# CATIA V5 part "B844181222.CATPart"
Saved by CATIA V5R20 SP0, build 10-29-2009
Part number: B844181222
Revision: 2
Definition: design
Nomenclature: B844181222
Source: made
Description: NOT SPECIFIED
Bounding box of the stored display mesh (mm): x -16.5 to 16.5, y -16.332 to 16.332, z -12 to 22
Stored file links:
  C:\Users\Utente\Desktop\3D files B844\B844181222.CATPart
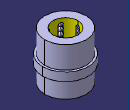
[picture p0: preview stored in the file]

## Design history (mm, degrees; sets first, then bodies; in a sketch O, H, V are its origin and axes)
Body1 "MANIFOLD_SOLID_BREP #38" (main body)
  Solid1: solid without history
Body2 "MANIFOLD_SOLID_BREP #76"
  Solid2: solid without history
Body3 "MANIFOLD_SOLID_BREP #114"
  Solid3: solid without history
Body4 "MANIFOLD_SOLID_BREP #152"
  Solid4: solid without history
Body5 "MANIFOLD_SOLID_BREP #190"
  Solid5: solid without history
Body6 "MANIFOLD_SOLID_BREP #228"
  Solid6: solid without history
Body7 "MANIFOLD_SOLID_BREP #266"
  Solid7: solid without history
Body8 "MANIFOLD_SOLID_BREP #1668"
  Solid8: solid without history
Body9 "MANIFOLD_SOLID_BREP #1706"
  Solid9: solid without history
Body10 "MANIFOLD_SOLID_BREP #1744"
  Solid10: solid without history
Body11 "MANIFOLD_SOLID_BREP #1782"
  Solid11: solid without history
Body12 "MANIFOLD_SOLID_BREP #1820"
  Solid12: solid without history
Body13 "MANIFOLD_SOLID_BREP #1858"
  Solid13: solid without history
Body14 "MANIFOLD_SOLID_BREP #1896"
  Solid14: solid without history
Body15 "MANIFOLD_SOLID_BREP #1934"
  Solid15: solid without history
Body16 "MANIFOLD_SOLID_BREP #1972"
  Solid16: solid without history
Body17 "MANIFOLD_SOLID_BREP #2010"
  Solid17: solid without history
Body18 "MANIFOLD_SOLID_BREP #2048"
  Solid18: solid without history
Body19 "MANIFOLD_SOLID_BREP #2086"
  Solid19: solid without history
Body20 "MANIFOLD_SOLID_BREP #2124"
  Solid20: solid without history
Body21 "MANIFOLD_SOLID_BREP #2162"
  Solid21: solid without history
Body22 "MANIFOLD_SOLID_BREP #2200"
  Solid22: solid without history
Body23 "MANIFOLD_SOLID_BREP #2238"
  Solid23: solid without history
Body24 "MANIFOLD_SOLID_BREP #2276"
  Solid24: solid without history
Body25 "MANIFOLD_SOLID_BREP #2314"
  Solid25: solid without history
Body26 "MANIFOLD_SOLID_BREP #2352"
  Solid26: solid without history
Body27 "MANIFOLD_SOLID_BREP #2390"
  Solid27: solid without history
Body28 "MANIFOLD_SOLID_BREP #2428"
  Solid28: solid without history
Body29 "MANIFOLD_SOLID_BREP #2466"
  Solid29: solid without history
Body30 "MANIFOLD_SOLID_BREP #2504"
  Solid30: solid without history
Body31 "MANIFOLD_SOLID_BREP #2542"
  Solid31: solid without history
Body32 "MANIFOLD_SOLID_BREP #2580"
  Solid32: solid without history
Body33 "MANIFOLD_SOLID_BREP #2618"
  Solid33: solid without history
Body34 "MANIFOLD_SOLID_BREP #2656"
  Solid34: solid without history
Body35 "MANIFOLD_SOLID_BREP #2694"
  Solid35: solid without history
Body36 "MANIFOLD_SOLID_BREP #2732"
  Solid36: solid without history
Body37 "MANIFOLD_SOLID_BREP #2770"
  Solid37: solid without history
Body38 "MANIFOLD_SOLID_BREP #2808"
  Solid38: solid without history
Body39 "MANIFOLD_SOLID_BREP #2846"
  Solid39: solid without history
Body40 "MANIFOLD_SOLID_BREP #2884"
  Solid40: solid without history
Body41 "MANIFOLD_SOLID_BREP #2922"
  Solid41: solid without history
Body42 "MANIFOLD_SOLID_BREP #2960"
  Solid42: solid without history
Body43 "MANIFOLD_SOLID_BREP #2998"
  Solid43: solid without history
Body44 "MANIFOLD_SOLID_BREP #3036"
  Solid44: solid without history
Body45 "MANIFOLD_SOLID_BREP #3074"
  Solid45: solid without history
Body46 "MANIFOLD_SOLID_BREP #3112"
  Solid46: solid without history
Body47 "MANIFOLD_SOLID_BREP #3150"
  Solid47: solid without history
Body48 "MANIFOLD_SOLID_BREP #3188"
  Solid48: solid without history
Body49 "MANIFOLD_SOLID_BREP #3226"
  Solid49: solid without history
Body50 "MANIFOLD_SOLID_BREP #3264"
  Solid50: solid without history
Body51 "MANIFOLD_SOLID_BREP #3302"
  Solid51: solid without history
Body52 "MANIFOLD_SOLID_BREP #3340"
  Solid52: solid without history
Body53 "MANIFOLD_SOLID_BREP #3378"
  Solid53: solid without history
Body54 "MANIFOLD_SOLID_BREP #3416"
  Solid54: solid without history
Body55 "MANIFOLD_SOLID_BREP #3454"
  Solid55: solid without history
